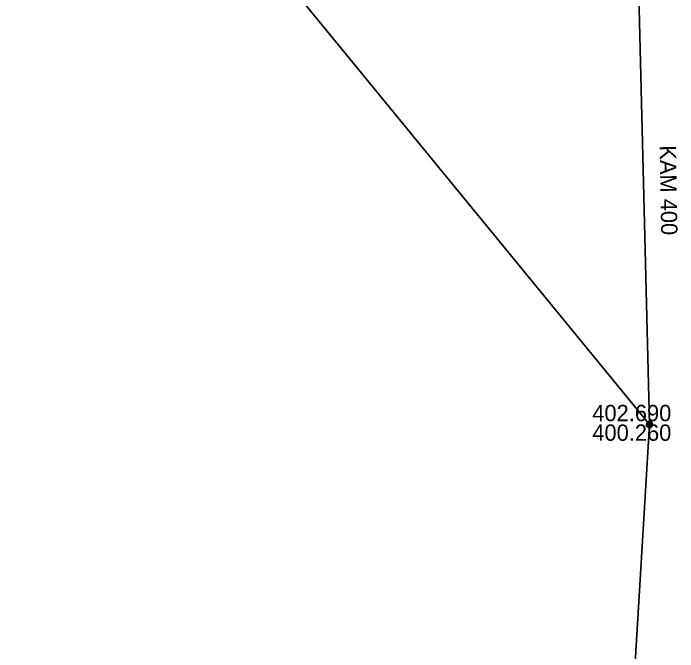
# Model space of a CAD drawing. Extents: x -873619 to -867639, y -1015082 to -1012326.
# Drawn here: x -867910.18 to -867865.47, y -1012859.98 to -1012817 of the extents above; entities that cross this region are included whole.
import ezdxf

# ---------------------------------------------------------------- set-up
doc = ezdxf.new("R2010")
doc.units = 0
doc.header["$LTSCALE"] = 0.44
for name, color, linetype, lineweight in [('1', 7, 'Continuous', 13), ('21', 7, 'Continuous', 35), ('32', 7, 'Continuous', 13)]:
    doc.layers.add(name, color=color, linetype=linetype, lineweight=lineweight)

msp = doc.modelspace()

# ---------------------------------------------------------------- linework, layer by layer
at = {"layer": '21'}
for points in [[(-867931.383, -1012770.263), (-867896.732, -1012808.835), (-867867.37, -1012844.68)], [(-867868.119, -1012814.87), (-867867.37, -1012844.68), (-867869.709, -1012883.46), (-867874.376, -1012932.352)]]:
    msp.add_lwpolyline(points, dxfattribs=at)
at = {"layer": '32'}
for points in [[(-867867.139, -1012844.68), (-867867.145, -1012844.628), (-867867.162, -1012844.578), (-867867.191, -1012844.534), (-867867.228, -1012844.497), (-867867.273, -1012844.47), (-867867.323, -1012844.453), (-867867.376, -1012844.449), (-867867.428, -1012844.456), (-867867.477, -1012844.475), (-867867.52, -1012844.504), (-867867.556, -1012844.543), (-867867.582, -1012844.588), (-867867.598, -1012844.639), (-867867.601, -1012844.691), (-867867.593, -1012844.743), (-867867.573, -1012844.792), (-867867.542, -1012844.835), (-867867.503, -1012844.869), (-867867.457, -1012844.895), (-867867.406, -1012844.909), (-867867.353, -1012844.911), (-867867.302, -1012844.901), (-867867.254, -1012844.88), (-867867.211, -1012844.849), (-867867.177, -1012844.808), (-867867.153, -1012844.762), (-867867.141, -1012844.711)], [(-867867.169, -1012844.68), (-867867.175, -1012844.631), (-867867.192, -1012844.585), (-867867.22, -1012844.545), (-867867.257, -1012844.513), (-867867.301, -1012844.491), (-867867.349, -1012844.48), (-867867.398, -1012844.48), (-867867.445, -1012844.493), (-867867.488, -1012844.517), (-867867.524, -1012844.55), (-867867.551, -1012844.591), (-867867.567, -1012844.638), (-867867.571, -1012844.687), (-867867.564, -1012844.735), (-867867.545, -1012844.78), (-867867.515, -1012844.82), (-867867.477, -1012844.851), (-867867.433, -1012844.871), (-867867.385, -1012844.881), (-867867.336, -1012844.879), (-867867.289, -1012844.864), (-867867.246, -1012844.839), (-867867.212, -1012844.805), (-867867.186, -1012844.763), (-867867.172, -1012844.716)], [(-867867.199, -1012844.68), (-867867.205, -1012844.635), (-867867.222, -1012844.593), (-867867.25, -1012844.558), (-867867.286, -1012844.531), (-867867.328, -1012844.514), (-867867.373, -1012844.509), (-867867.418, -1012844.515), (-867867.459, -1012844.534), (-867867.494, -1012844.562), (-867867.521, -1012844.599), (-867867.537, -1012844.641), (-867867.541, -1012844.686), (-867867.534, -1012844.731), (-867867.515, -1012844.772), (-867867.486, -1012844.806), (-867867.449, -1012844.832), (-867867.406, -1012844.848), (-867867.361, -1012844.851), (-867867.316, -1012844.843), (-867867.276, -1012844.823), (-867867.242, -1012844.794), (-867867.216, -1012844.756), (-867867.202, -1012844.713)], [(-867867.229, -1012844.68), (-867867.233, -1012844.639), (-867867.252, -1012844.602), (-867867.279, -1012844.571), (-867867.314, -1012844.55), (-867867.354, -1012844.539), (-867867.395, -1012844.541), (-867867.434, -1012844.554), (-867867.468, -1012844.578), (-867867.493, -1012844.61), (-867867.508, -1012844.648), (-867867.511, -1012844.689), (-867867.503, -1012844.729), (-867867.483, -1012844.765), (-867867.454, -1012844.794), (-867867.417, -1012844.813), (-867867.377, -1012844.821), (-867867.336, -1012844.817), (-867867.298, -1012844.802), (-867867.266, -1012844.776), (-867867.243, -1012844.742), (-867867.23, -1012844.703)], [(-867867.259, -1012844.68), (-867867.264, -1012844.644), (-867867.282, -1012844.612), (-867867.308, -1012844.587), (-867867.342, -1012844.572), (-867867.378, -1012844.569), (-867867.413, -1012844.577), (-867867.444, -1012844.597), (-867867.467, -1012844.625), (-867867.48, -1012844.659), (-867867.48, -1012844.696), (-867867.469, -1012844.731), (-867867.448, -1012844.76), (-867867.418, -1012844.781), (-867867.383, -1012844.791), (-867867.346, -1012844.789), (-867867.312, -1012844.775), (-867867.285, -1012844.752), (-867867.266, -1012844.72), (-867867.259, -1012844.685)], [(-867867.289, -1012844.68), (-867867.294, -1012844.649), (-867867.311, -1012844.623), (-867867.337, -1012844.606), (-867867.367, -1012844.599), (-867867.398, -1012844.603), (-867867.425, -1012844.62), (-867867.443, -1012844.644), (-867867.451, -1012844.675), (-867867.447, -1012844.705), (-867867.432, -1012844.733), (-867867.407, -1012844.752), (-867867.378, -1012844.761), (-867867.347, -1012844.758), (-867867.319, -1012844.744), (-867867.299, -1012844.72), (-867867.289, -1012844.691)], [(-867867.319, -1012844.68), (-867867.324, -1012844.656), (-867867.341, -1012844.638), (-867867.364, -1012844.629), (-867867.388, -1012844.632), (-867867.409, -1012844.646), (-867867.42, -1012844.668), (-867867.42, -1012844.693), (-867867.407, -1012844.714), (-867867.388, -1012844.728), (-867867.363, -1012844.731), (-867867.34, -1012844.722), (-867867.324, -1012844.704)], [(-867867.349, -1012844.68), (-867867.354, -1012844.665), (-867867.369, -1012844.659), (-867867.384, -1012844.663), (-867867.391, -1012844.677), (-867867.387, -1012844.692), (-867867.374, -1012844.701), (-867867.358, -1012844.698), (-867867.349, -1012844.686)]]:
    msp.add_lwpolyline(points, close=True, dxfattribs=at)

# ---------------------------------------------------------------- texts
at = {"layer": '1'}
msp.add_text('KAM 400 ', height=1.1, rotation=271, dxfattribs=at).set_placement((-867866.691, -1012825.897))
for s, p in [('402.690 ', (-867871.22, -1012844.46)), ('400.260 ', (-867871.22, -1012845.78))]:
    msp.add_text(s, height=1.1, dxfattribs=at).set_placement(p)

doc.saveas('drawing.dxf')
